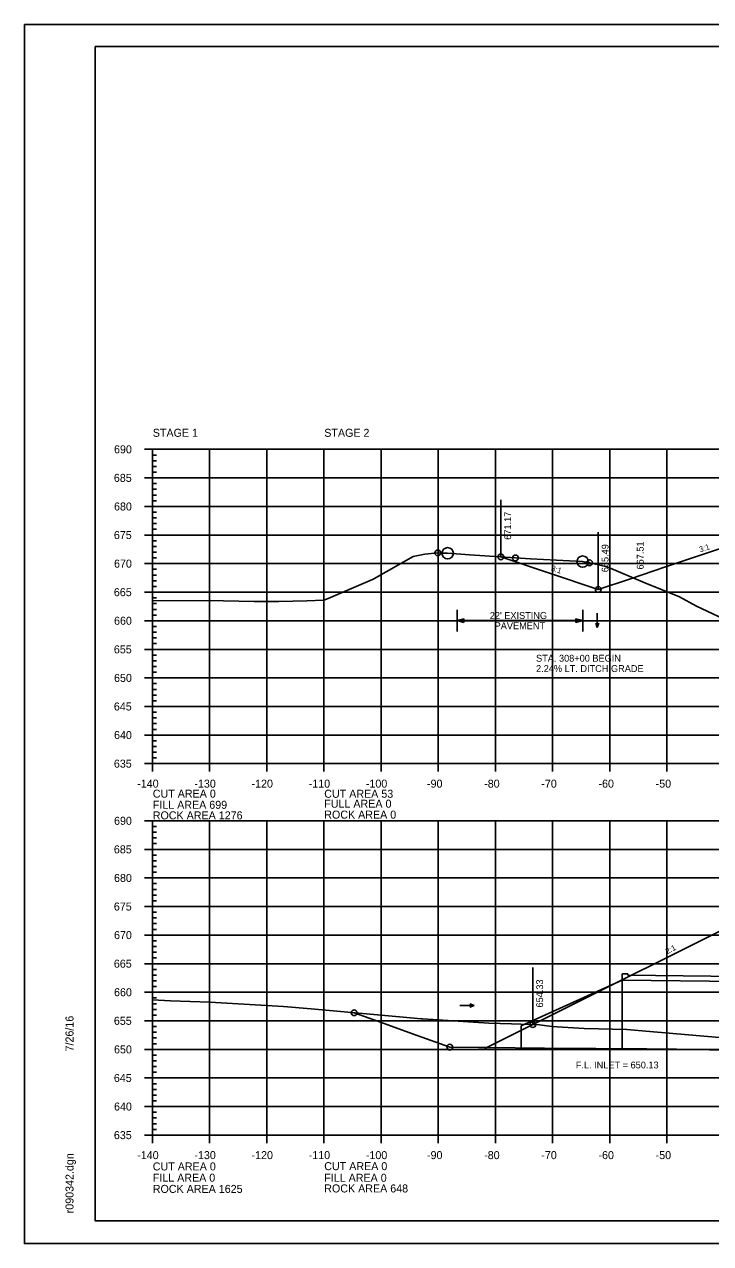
# Model space of a CAD drawing. Extents: x 1370515 to 1370849, y 383299 to 386073.
# Drawn here: x 1370515.4 to 1370635.5, y 384366.1 to 384579.5 of the extents above; entities that cross this region are included whole.
import ezdxf

# ---------------------------------------------------------------- set-up
doc = ezdxf.new("R2010")
doc.units = 0
for name, color, linetype in [('R_Axis', 7, 'Continuous'), ('R_Axis Annot', 7, 'Continuous'), ('R_Border', 7, 'Continuous'), ('R_Drive', 7, 'Continuous'), ('R_Exist Surface', 7, 'Continuous'), ('R_Fin Surface', 7, 'Continuous'), ('R_Grid', 7, 'Continuous'), ('R_No Plot', 7, 'Continuous'), ('R_ROW Annot', 7, 'Continuous'), ('R_Water', 7, 'Continuous'), ('R_Water Annot', 7, 'Continuous'), ('R_Xsect Elev', 7, 'Continuous'), ('R_Xsect Slope', 7, 'Continuous')]:
    doc.layers.add(name, color=color, linetype=linetype)

msp = doc.modelspace()

# ---------------------------------------------------------------- linework, layer by layer
at = {"layer": 'R_Axis'}
for p, q in [((1370536.4, 384505.1), (1370539.2, 384505.1)), ((1370537.8, 384450.1), (1370537.8, 384505.1)), ((1370537.8, 384504.1), (1370538.5, 384504.1)), ((1370537.8, 384503.1), (1370538.5, 384503.1)), ((1370537.8, 384502.1), (1370538.5, 384502.1)), ((1370537.8, 384501.1), (1370538.5, 384501.1)), ((1370536.4, 384500.1), (1370539.2, 384500.1)), ((1370537.8, 384499.1), (1370538.5, 384499.1)), ((1370537.8, 384498.1), (1370538.5, 384498.1)), ((1370537.8, 384497.1), (1370538.5, 384497.1)), ((1370536.4, 384495.1), (1370539.2, 384495.1)), ((1370537.8, 384496.1), (1370538.5, 384496.1)), ((1370537.8, 384494.1), (1370538.5, 384494.1)), ((1370537.8, 384493.1), (1370538.5, 384493.1)), ((1370537.8, 384492.1), (1370538.5, 384492.1)), ((1370536.4, 384490.1), (1370539.2, 384490.1)), ((1370537.8, 384491.1), (1370538.5, 384491.1)), ((1370537.8, 384489.1), (1370538.5, 384489.1)), ((1370537.8, 384488.1), (1370538.5, 384488.1)), ((1370537.8, 384487.1), (1370538.5, 384487.1)), ((1370537.8, 384486.1), (1370538.5, 384486.1)), ((1370536.4, 384485.1), (1370539.2, 384485.1)), ((1370537.8, 384484.1), (1370538.5, 384484.1)), ((1370537.8, 384483.1), (1370538.5, 384483.1)), ((1370537.8, 384482.1), (1370538.5, 384482.1)), ((1370536.4, 384480.1), (1370539.2, 384480.1)), ((1370537.8, 384481.1), (1370538.5, 384481.1)), ((1370537.8, 384479.1), (1370538.5, 384479.1)), ((1370537.8, 384478.1), (1370538.5, 384478.1)), ((1370537.8, 384477.1), (1370538.5, 384477.1)), ((1370536.4, 384475.1), (1370539.2, 384475.1)), ((1370537.8, 384476.1), (1370538.5, 384476.1)), ((1370537.8, 384474.1), (1370538.5, 384474.1)), ((1370537.8, 384473.1), (1370538.5, 384473.1)), ((1370537.8, 384472.1), (1370538.5, 384472.1)), ((1370537.8, 384471.1), (1370538.5, 384471.1)), ((1370536.4, 384470.1), (1370539.2, 384470.1)), ((1370537.8, 384469.1), (1370538.5, 384469.1)), ((1370537.8, 384468.1), (1370538.5, 384468.1)), ((1370537.8, 384467.1), (1370538.5, 384467.1)), ((1370536.4, 384465.1), (1370539.2, 384465.1)), ((1370537.8, 384466.1), (1370538.5, 384466.1)), ((1370537.8, 384464.1), (1370538.5, 384464.1)), ((1370537.8, 384463.1), (1370538.5, 384463.1)), ((1370537.8, 384462.1), (1370538.5, 384462.1)), ((1370536.4, 384460.1), (1370539.2, 384460.1)), ((1370537.8, 384461.1), (1370538.5, 384461.1)), ((1370537.8, 384459.1), (1370538.5, 384459.1)), ((1370537.8, 384458.1), (1370538.5, 384458.1)), ((1370537.8, 384457.1), (1370538.5, 384457.1)), ((1370537.8, 384456.1), (1370538.5, 384456.1)), ((1370536.4, 384455.1), (1370539.2, 384455.1)), ((1370537.8, 384454.1), (1370538.5, 384454.1)), ((1370537.8, 384453.1), (1370538.5, 384453.1)), ((1370537.8, 384452.1), (1370538.5, 384452.1)), ((1370537.8, 384448.7), (1370537.8, 384451.5)), ((1370547.8, 384448.7), (1370547.8, 384451.5)), ((1370557.8, 384448.7), (1370557.8, 384451.5)), ((1370567.8, 384448.7), (1370567.8, 384451.5)), ((1370577.8, 384448.7), (1370577.8, 384451.5)), ((1370587.8, 384448.7), (1370587.8, 384451.5)), ((1370597.8, 384448.7), (1370597.8, 384451.5)), ((1370607.8, 384448.7), (1370607.8, 384451.5)), ((1370617.8, 384448.7), (1370617.8, 384451.5)), ((1370627.8, 384448.7), (1370627.8, 384451.5)), ((1370536.4, 384450.1), (1370539.2, 384450.1)), ((1370537.8, 384451.1), (1370538.5, 384451.1)), ((1370537.8, 384450.1), (1370817.8, 384450.1)), ((1370536.4, 384440.1), (1370539.2, 384440.1)), ((1370537.8, 384385.1), (1370537.8, 384440.1)), ((1370537.8, 384439.1), (1370538.5, 384439.1)), ((1370537.8, 384438.1), (1370538.5, 384438.1)), ((1370537.8, 384437.1), (1370538.5, 384437.1)), ((1370536.4, 384435.1), (1370539.2, 384435.1)), ((1370537.8, 384436.1), (1370538.5, 384436.1)), ((1370537.8, 384434.1), (1370538.5, 384434.1)), ((1370537.8, 384433.1), (1370538.5, 384433.1)), ((1370536.4, 384430.1), (1370539.2, 384430.1)), ((1370537.8, 384432.1), (1370538.5, 384432.1)), ((1370537.8, 384431.1), (1370538.5, 384431.1)), ((1370537.8, 384429.1), (1370538.5, 384429.1)), ((1370537.8, 384428.1), (1370538.5, 384428.1)), ((1370537.8, 384427.1), (1370538.5, 384427.1)), ((1370537.8, 384426.1), (1370538.5, 384426.1)), ((1370536.4, 384425.1), (1370539.2, 384425.1)), ((1370537.8, 384424.1), (1370538.5, 384424.1)), ((1370537.8, 384423.1), (1370538.5, 384423.1)), ((1370537.8, 384422.1), (1370538.5, 384422.1)), ((1370536.4, 384420.1), (1370539.2, 384420.1)), ((1370537.8, 384421.1), (1370538.5, 384421.1)), ((1370537.8, 384419.1), (1370538.5, 384419.1)), ((1370537.8, 384418.1), (1370538.5, 384418.1)), ((1370537.8, 384417.1), (1370538.5, 384417.1)), ((1370537.8, 384416.1), (1370538.5, 384416.1)), ((1370536.4, 384415.1), (1370539.2, 384415.1)), ((1370537.8, 384414.1), (1370538.5, 384414.1)), ((1370537.8, 384413.1), (1370538.5, 384413.1)), ((1370537.8, 384412.1), (1370538.5, 384412.1)), ((1370537.8, 384411.1), (1370538.5, 384411.1)), ((1370536.4, 384410.1), (1370539.2, 384410.1)), ((1370537.8, 384409.1), (1370538.5, 384409.1)), ((1370537.8, 384408.1), (1370538.5, 384408.1)), ((1370537.8, 384407.1), (1370538.5, 384407.1)), ((1370536.4, 384405.1), (1370539.2, 384405.1)), ((1370537.8, 384406.1), (1370538.5, 384406.1)), ((1370537.8, 384404.1), (1370538.5, 384404.1)), ((1370537.8, 384403.1), (1370538.5, 384403.1)), ((1370537.8, 384402.1), (1370538.5, 384402.1)), ((1370537.8, 384401.1), (1370538.5, 384401.1)), ((1370536.4, 384400.1), (1370539.2, 384400.1)), ((1370537.8, 384399.1), (1370538.5, 384399.1)), ((1370537.8, 384398.1), (1370538.5, 384398.1)), ((1370537.8, 384397.1), (1370538.5, 384397.1)), ((1370537.8, 384396.1), (1370538.5, 384396.1)), ((1370536.4, 384395.1), (1370539.2, 384395.1)), ((1370537.8, 384394.1), (1370538.5, 384394.1)), ((1370537.8, 384393.1), (1370538.5, 384393.1)), ((1370537.8, 384392.1), (1370538.5, 384392.1)), ((1370536.4, 384390.1), (1370539.2, 384390.1)), ((1370537.8, 384391.1), (1370538.5, 384391.1)), ((1370537.8, 384389.1), (1370538.5, 384389.1)), ((1370537.8, 384388.1), (1370538.5, 384388.1)), ((1370537.8, 384387.1), (1370538.5, 384387.1)), ((1370537.8, 384383.7), (1370537.8, 384386.5)), ((1370537.8, 384386.1), (1370538.5, 384386.1)), ((1370547.8, 384383.7), (1370547.8, 384386.5)), ((1370557.8, 384383.7), (1370557.8, 384386.5)), ((1370567.8, 384383.7), (1370567.8, 384386.5)), ((1370577.8, 384383.7), (1370577.8, 384386.5)), ((1370587.8, 384383.7), (1370587.8, 384386.5)), ((1370597.8, 384383.7), (1370597.8, 384386.5)), ((1370607.8, 384383.7), (1370607.8, 384386.5)), ((1370617.8, 384383.7), (1370617.8, 384386.5)), ((1370627.8, 384383.7), (1370627.8, 384386.5)), ((1370536.4, 384385.1), (1370539.2, 384385.1)), ((1370537.8, 384385.1), (1370817.8, 384385.1))]:
    msp.add_line(p, q, dxfattribs=at)
at = {"layer": 'R_Border'}
for p, q in [((1370527.8, 384575.56), (1370843.98, 384575.56)), ((1370527.8, 384370.1), (1370527.8, 384575.56)), ((1370527.8, 384370.1), (1370527.8, 384370.1)), ((1370843.98, 384370.1), (1370527.8, 384370.1))]:
    msp.add_line(p, q, dxfattribs=at)
at = {"layer": 'R_Exist Surface'}
for points in [[(1370537.8, 384478.64), (1370537.81, 384478.64), (1370550.21, 384478.56), (1370555.6, 384478.5), (1370559.93, 384478.46), (1370564.84, 384478.6), (1370567.76, 384478.69), (1370568.52, 384478.97), (1370575.51, 384481.99), (1370576.32, 384482.32), (1370576.55, 384482.45), (1370583.41, 384486.37), (1370585.46, 384486.75), (1370587.72, 384486.97), (1370588.53, 384486.91), (1370589.45, 384486.91), (1370593.3, 384486.64), (1370601.31, 384486.09), (1370603.93, 384485.91), (1370613.07, 384485.45), (1370613.96, 384485.28), (1370614.28, 384485.26), (1370615.09, 384485.08), (1370617.35, 384484.55), (1370623.94, 384481.76), (1370630.02, 384479.26), (1370633, 384477.65), (1370639.72, 384474.53)], [(1370537.8, 384408.78), (1370540.94, 384408.61), (1370547.85, 384408.37), (1370560.74, 384407.58), (1370565.56, 384407.22), (1370583.62, 384405.56), (1370584.82, 384405.44), (1370585.04, 384405.43), (1370596.67, 384404.69), (1370600.6, 384404.6), (1370605.5, 384404.38), (1370607.66, 384404.09), (1370613.33, 384403.73), (1370620.78, 384403.57), (1370624.14, 384403.29), (1370642.42, 384401.7)]]:
    msp.add_lwpolyline(points, dxfattribs=at)
at = {"layer": 'R_Fin Surface'}
for points in [[(1370598.76, 384486.27), (1370615.8, 384480.59), (1370621.44, 384482.45), (1370627.58, 384484.55), (1370651.8, 384492.59), (1370657.8, 384494.09), (1370665.8, 384493.29), (1370677.8, 384492.09), (1370689.8, 384490.89), (1370697.8, 384490.09), (1370703.8, 384488.59), (1370708.65, 384486.16), (1370752.73, 384464.12)], [(1370595.96, 384400.23), (1370651.8, 384428.15), (1370657.8, 384429.65), (1370665.8, 384428.86), (1370677.8, 384427.67), (1370689.8, 384426.47), (1370697.8, 384425.68), (1370703.8, 384424.18), (1370708.67, 384421.75), (1370716.93, 384417.62), (1370754.29, 384398.93)], [(1370573.09, 384406.52), (1370575.72, 384405.58), (1370577.73, 384404.85), (1370583.32, 384402.83), (1370589.82, 384400.49), (1370594.86, 384400.44), (1370596.2, 384400.43), (1370606.41, 384400.34), (1370613.86, 384400.27), (1370615.38, 384400.26), (1370622.11, 384400.2), (1370624.31, 384400.18), (1370628.76, 384400.14), (1370629.14, 384400.14), (1370629.51, 384400.14), (1370634.42, 384400.09), (1370641.05, 384400.03)]]:
    msp.add_lwpolyline(points, dxfattribs=at)
at = {"layer": 'R_Grid'}
for p, q in [((1370537.8, 384505.1), (1370817.8, 384505.1)), ((1370537.8, 384450.1), (1370537.8, 384505.1)), ((1370547.8, 384450.1), (1370547.8, 384505.1)), ((1370557.8, 384450.1), (1370557.8, 384505.1)), ((1370567.8, 384450.1), (1370567.8, 384505.1)), ((1370577.8, 384450.1), (1370577.8, 384505.1)), ((1370587.8, 384450.1), (1370587.8, 384505.1)), ((1370597.8, 384450.1), (1370597.8, 384505.1)), ((1370607.8, 384450.1), (1370607.8, 384505.1)), ((1370617.8, 384450.1), (1370617.8, 384505.1)), ((1370627.8, 384450.1), (1370627.8, 384505.1)), ((1370537.8, 384500.1), (1370817.8, 384500.1)), ((1370537.8, 384495.1), (1370817.8, 384495.1)), ((1370537.8, 384490.1), (1370817.8, 384490.1)), ((1370537.8, 384485.1), (1370817.8, 384485.1)), ((1370537.8, 384480.1), (1370817.8, 384480.1)), ((1370537.8, 384475.1), (1370817.8, 384475.1)), ((1370537.8, 384470.1), (1370817.8, 384470.1)), ((1370537.8, 384465.1), (1370817.8, 384465.1)), ((1370537.8, 384460.1), (1370817.8, 384460.1)), ((1370537.8, 384455.1), (1370817.8, 384455.1)), ((1370537.8, 384450.1), (1370817.8, 384450.1)), ((1370537.8, 384440.1), (1370817.8, 384440.1)), ((1370537.8, 384385.1), (1370537.8, 384440.1)), ((1370547.8, 384385.1), (1370547.8, 384440.1)), ((1370557.8, 384385.1), (1370557.8, 384440.1)), ((1370567.8, 384385.1), (1370567.8, 384440.1)), ((1370577.8, 384385.1), (1370577.8, 384440.1)), ((1370587.8, 384385.1), (1370587.8, 384440.1)), ((1370597.8, 384385.1), (1370597.8, 384440.1)), ((1370607.8, 384385.1), (1370607.8, 384440.1)), ((1370617.8, 384385.1), (1370617.8, 384440.1)), ((1370627.8, 384385.1), (1370627.8, 384440.1)), ((1370537.8, 384435.1), (1370817.8, 384435.1)), ((1370537.8, 384430.1), (1370817.8, 384430.1)), ((1370537.8, 384425.1), (1370817.8, 384425.1)), ((1370537.8, 384420.1), (1370817.8, 384420.1)), ((1370537.8, 384415.1), (1370817.8, 384415.1)), ((1370537.8, 384410.1), (1370817.8, 384410.1)), ((1370537.8, 384405.1), (1370817.8, 384405.1)), ((1370537.8, 384400.1), (1370817.8, 384400.1)), ((1370537.8, 384395.1), (1370817.8, 384395.1)), ((1370537.8, 384390.1), (1370817.8, 384390.1)), ((1370537.8, 384385.1), (1370817.8, 384385.1))]:
    msp.add_line(p, q, dxfattribs=at)
at = {"layer": 'R_No Plot'}
for p, q in [((1370515.4, 384579.45), (1370848.73, 384579.45)), ((1370515.4, 384366.12), (1370848.73, 384366.12))]:
    msp.add_line(p, q, dxfattribs=at)
for points in [[(1370515.39, 384579.45), (1370848.73, 384579.45), (1370848.73, 384366.12), (1370515.39, 384366.12)], [(1370761.72, 384575.56), (1370761.72, 384565.68), (1370797.45, 384565.68), (1370797.45, 384562.76), (1370820.65, 384562.76), (1370820.65, 384539.54), (1370843.98, 384539.54), (1370843.98, 384370.1), (1370527.8, 384370.1), (1370527.8, 384575.56)]]:
    msp.add_lwpolyline(points, close=True, dxfattribs=at)
for centre, radius in [((1370589.45, 384486.91), 1), ((1370587.72, 384486.97), 0.5), ((1370598.76, 384486.27), 0.5), ((1370601.31, 384486.09), 0.5), ((1370613.07, 384485.45), 1), ((1370614.28, 384485.26), 0.5), ((1370615.8, 384480.59), 0.5), ((1370573.09, 384406.52), 0.5), ((1370604.35, 384404.43), 0.5), ((1370589.82, 384400.49), 0.5), ((1370589.82, 384400.49), 0.5)]:
    msp.add_circle(centre, radius, dxfattribs=at)
at = {"layer": 'R_ROW Annot'}
for p, q in [((1370591.09, 384473.23), (1370591.09, 384477)), ((1370613.09, 384475.12), (1370591.09, 384475.12)), ((1370613.09, 384473.23), (1370613.09, 384477))]:
    msp.add_line(p, q, dxfattribs=at)
for points in [[(1370592.29, 384474.82), (1370591.09, 384475.12), (1370592.29, 384475.42)], [(1370611.89, 384475.42), (1370613.09, 384475.12), (1370611.89, 384474.82)]]:
    msp.add_lwpolyline(points, close=True, dxfattribs=at)
at = {"layer": 'R_Water'}
for p, q in [((1370619.98, 384413.34), (1370620.98, 384413.34)), ((1370619.98, 384413.34), (1370619.98, 384412.22)), ((1370620.98, 384413.34), (1370620.98, 384413.09)), ((1370620.98, 384413.09), (1370729.33, 384411.79)), ((1370602.31, 384404.22), (1370619.98, 384412.22)), ((1370619.98, 384412.22), (1370619.98, 384400.22)), ((1370619.98, 384412.22), (1370730.33, 384410.92)), ((1370602.31, 384404.22), (1370602.31, 384400.22)), ((1370602.31, 384400.22), (1370619.98, 384400.22)), ((1370619.98, 384400.22), (1370730.33, 384398.92))]:
    msp.add_line(p, q, dxfattribs=at)
at = {"layer": 'R_Water Annot'}
for p, q in [((1370615.63, 384476.44), (1370615.63, 384473.92)), ((1370615.63, 384473.92), (1370615.35, 384474.69)), ((1370615.63, 384473.92), (1370615.91, 384474.69)), ((1370591.57, 384407.77), (1370594.08, 384407.77)), ((1370594.08, 384407.77), (1370593.31, 384408.05)), ((1370594.08, 384407.77), (1370593.31, 384407.49))]:
    msp.add_line(p, q, dxfattribs=at)
at = {"layer": 'R_Xsect Elev'}
for p, q in [((1370598.76, 384486.27), (1370598.76, 384496.27)), ((1370615.8, 384480.59), (1370615.8, 384490.59)), ((1370604.35, 384404.43), (1370604.35, 384414.43))]:
    msp.add_line(p, q, dxfattribs=at)

# ---------------------------------------------------------------- texts
at = {"layer": 'R_Axis'}
for p in [(1370537.8, 384450.1), (1370537.8, 384385.1)]:
    msp.add_text('-', height=0.0001, dxfattribs=at).set_placement(p)
at = {"layer": 'R_Axis Annot'}
for s, p in [('STAGE 1', (1370537.86, 384507.29)), ('STAGE 2', (1370567.86, 384507.29)), ('690', (1370531.08, 384504.4)), ('685', (1370531.05, 384499.4)), ('680', (1370531.08, 384494.4)), ('675', (1370531.05, 384489.4)), ('670', (1370531.08, 384484.4)), ('665', (1370531.05, 384479.4)), ('660', (1370531.08, 384474.4)), ('655', (1370531.05, 384469.4)), ('650', (1370531.08, 384464.4)), ('645', (1370531.05, 384459.4)), ('640', (1370531.08, 384454.4)), ('635', (1370531.05, 384449.4)), ('-140', (1370535.14, 384445.9)), ('-130', (1370545.14, 384445.9)), ('-120', (1370555.14, 384445.9)), ('-110', (1370565.14, 384445.9)), ('-100', (1370575.14, 384445.9)), ('-90', (1370585.84, 384445.9)), ('-80', (1370595.84, 384445.9)), ('-70', (1370605.84, 384445.9)), ('-60', (1370615.84, 384445.9)), ('-50', (1370625.84, 384445.9)), ('CUT AREA 0', (1370537.86, 384444.15)), ('CUT AREA 53', (1370567.86, 384444.13)), ('FILL AREA 699', (1370537.86, 384442.2)), ('FULL AREA 0', (1370567.86, 384442.39)), ('690', (1370531.08, 384439.4)), ('ROCK AREA 1276', (1370537.86, 384440.35)), ('ROCK AREA 0', (1370567.86, 384440.48)), ('685', (1370531.05, 384434.4)), ('680', (1370531.08, 384429.4)), ('675', (1370531.05, 384424.4)), ('670', (1370531.08, 384419.4)), ('665', (1370531.05, 384414.4)), ('660', (1370531.08, 384409.4)), ('655', (1370531.05, 384404.4)), ('650', (1370531.08, 384399.4)), ('645', (1370531.05, 384394.4)), ('640', (1370531.08, 384389.4)), ('635', (1370531.05, 384384.4)), ('-140', (1370535.14, 384380.9)), ('-130', (1370545.14, 384380.9)), ('-120', (1370555.14, 384380.9)), ('-110', (1370565.14, 384380.9)), ('-100', (1370575.14, 384380.9)), ('-90', (1370585.84, 384380.9)), ('-80', (1370595.84, 384380.9)), ('-70', (1370605.84, 384380.9)), ('-60', (1370615.84, 384380.9)), ('-50', (1370625.84, 384380.9)), ('CUT AREA 0', (1370537.86, 384378.92)), ('CUT AREA 0', (1370567.86, 384378.97)), ('FILL AREA 0', (1370537.86, 384376.95)), ('FILL AREA 0', (1370567.86, 384376.94)), ('ROCK AREA 1625', (1370537.86, 384374.99)), ('ROCK AREA 648', (1370567.86, 384375.07))]:
    msp.add_text(s, height=1.4, dxfattribs=at).set_placement(p)
at = {"layer": 'R_Border'}
for s, p in [('7/26/16', (1370523.99, 384399.74)), ('r090342.dgn', (1370523.99, 384371.42))]:
    msp.add_text(s, height=1.4, rotation=90, dxfattribs=at).set_placement(p)
at = {"layer": 'R_Drive'}
for s, p in [('STA. 308+00 BEGIN', (1370604.92, 384467.94)), ('2.24% LT. DITCH GRADE', (1370604.92, 384466.14)), ('F.L. INLET = 650.13', (1370611.87, 384396.77))]:
    msp.add_text(s, height=1.2, dxfattribs=at).set_placement(p)
at = {"layer": 'R_No Plot'}
for p in [(1370583.37, 384486.32), (1370617.31, 384484.5), (1370576.28, 384482.27), (1370629.97, 384479.21), (1370537.76, 384478.59), (1370559.89, 384478.41), (1370567.72, 384478.64), (1370560.7, 384407.53), (1370584.77, 384405.39), (1370600.55, 384404.55), (1370620.74, 384403.52)]:
    msp.add_text('+', height=0.1, dxfattribs=at).set_placement(p)
at = {"layer": 'R_ROW Annot'}
for s, p in [("22' EXISTING", (1370596.82, 384475.42)), ('PAVEMENT', (1370597.67, 384473.62))]:
    msp.add_text(s, height=1.2, dxfattribs=at).set_placement(p)
at = {"layer": 'R_Xsect Elev'}
for s, p in [('671.17', (1370600.56, 384489.27)), ('665.49', (1370617.6, 384483.59)), ('667.51', (1370623.74, 384484.07)), ('654.33', (1370606.15, 384407.43))]:
    msp.add_text(s, height=1.2, rotation=90, dxfattribs=at).set_placement(p)
at = {"layer": 'R_Xsect Slope'}
for s, rotation, p in [('3:1', 18.4349, (1370633.64, 384487.06)), ('3:1', 341.5651, (1370607.44, 384483.9)), ('2:1', 26.5651, (1370627.85, 384416.74))]:
    msp.add_text(s, height=1, rotation=rotation, dxfattribs=at).set_placement(p)

doc.saveas('drawing.dxf')
